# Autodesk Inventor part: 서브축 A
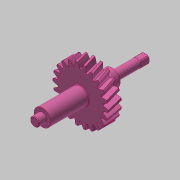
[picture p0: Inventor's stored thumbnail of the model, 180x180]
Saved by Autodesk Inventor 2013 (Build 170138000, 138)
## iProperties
Created: 2017-11
Part Number: 서브축 A
Material: 강철, 탄소
Document SubType Name: Modeling
Designer: mduedu
Categories: <?xml version="1.0" encoding="UTF-16"?> <MemberInstance><Categories><FamilyTemplate><FamilyTemplateParameter ValueType="xs:double" Id="1" ObjectReferenceKey="da
Density: 1 g/cm^3
CustomPartVersion: 1
Author: mduedu
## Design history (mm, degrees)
sketch "Sketch1"
  geometry: C1 r 24.776 at (0, 0)
  constraints: 1 centre point
  dimensions: "d0" = 49.55215 diameter of C1 (= da_da)
extrude "Extrusion1" new body sketch "Sketch1" distance "d1" = 12 (= da_b); taper "d2" = 0 deg
workplane "Work Plane2"
sketch "Sketch2"
  geometry: C1 r 24.776 at (0, 0) reference; C2 r 22.776 at (0, 0)
  constraints: 1 centre point, 1 coincident
  dimensions: "d3" = 45.55215 diameter of C2 (= da_dw)
feature "피치 지름" sketch "Sketch2" dims "d4" = 10, "d5" = 0
workplane "Work Plane8"
workplane "Work Plane9"
feature "스퍼 기어" dims "da_b" = 12, "da_d" = 45.55215, "da_aw" = 54.86964, "da_da" = 49.55215, "da_df" = 40.55215, "da_dw" = 45.55215, angle "da_beta" = 15 deg, "da_lefttooth" = 10, "da_righttooth" = 0
sketch "스케치3"
  geometry: C1 r 7.5 at (0, 0); 1 further point
  constraints: 1 centre point, 1 coincident
  dimensions: "d49" = 15 diameter of C1
extrude "돌출2" join sketch "스케치3" distance "d50" = 34; taper "d51" = 0 deg
sketch "스케치4"
  geometry: C1 r 4 at (0, 0); 1 further point
  constraints: 1 centre point, 1 coincident
  dimensions: "d52" = 8 diameter of C1
extrude "돌출3" join sketch "스케치4" distance "d53" = 7; taper "d54" = 0 deg
sketch "스케치5"
  geometry: C1 r 7.5 at (0, 0); 1 further point
  constraints: 1 centre point, 1 coincident
  dimensions: "d55" = 15 diameter of C1
extrude "돌출4" join sketch "스케치5" distance "d56" = 16; taper "d57" = 0 deg
sketch "스케치6"
  geometry: C1 r 4 at (0, 0); 1 further point
  constraints: 1 centre point, 1 coincident
  dimensions: "d58" = 8 diameter of C1
extrude "돌출5" join sketch "스케치6" distance "d59" = 30; taper "d60" = 0 deg
chamfer "모따기1" distance "d61" = 0.5; stored, may be unused: second distance "d62" = 2, angle "d63" = 45 deg
fillet "모깎기1" dims "d64" = 0.5
sketch "스케치7"
  geometry: L1 (-3.25, -3.25)-(3.25, -3.25); L2 (3.25, -3.25)-(3.25, 3.25); L3 (3.25, 3.25)-(-3.25, 3.25); L4 (-3.25, 3.25)-(-3.25, -3.25); L5 (-3.25, -3.25)-(3.25, 3.25); L6 (3.25, -3.25)-(-3.25, 3.25); L7 (-5, -5)-(5, -5); L8 (5, -5)-(5, 5); L9 (5, 5)-(-5, 5); L10 (-5, 5)-(-5, -5); L11 (-5, -5)-(5, 5); L12 (5, -5)-(-5, 5); 1 further point
  constraints: 24 end point, 4 midpoint, 4 parallel, 2 horizontal, 2 perpendicular
  dimensions: "d65" = 6.5 distance of L3.end L2.end; "d66" = 6.5 distance of L2.end L1.end; "d67" = 10 distance of L9.end L8.end; "d68" = 10 distance of L8.end L7.end
extrude "돌출6" cut sketch "스케치7" distance "d69" = 8; taper "d70" = 0 deg
body "Solid1"
body "Srf1"
other parameters: "d16" = 54.86964 (= da_aw), "d17" = 0, "d34" = 1.428 (computed from da_z), "d39" = 0, "d41" = 0, "d43" = 54.86964 (= da_aw), "d46" = 54.86964 (= da_aw), "d47" = 0, "d48" = 0
